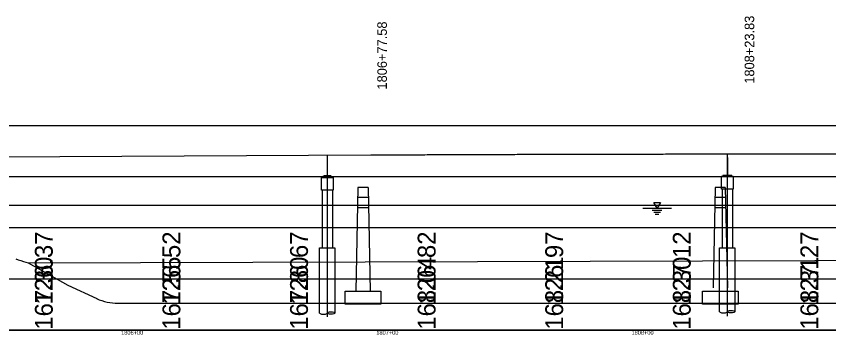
# Model space of a CAD drawing. Extents: x 2126510 to 2136144, y 865066 to 868066.
# Drawn here: x 2129003.4 to 2129321.8, y 866612.1 to 866736.8 of the extents above; entities that cross this region are included whole.
import ezdxf

# ---------------------------------------------------------------- set-up
doc = ezdxf.new("R2010")
doc.units = 0
for name, color, linetype in [('RD_DTM_BkLn1', 7, 'Continuous'), ('RD_EX_BldgApp', 7, 'Continuous'), ('RD_EX_Bridge', 7, 'Continuous'), ('RD_EX_GuardRail', 7, 'Continuous'), ('RD_EX_H2O', 7, 'Continuous'), ('RD_EX_Misc', 7, 'Continuous'), ('RD_EX_Misc_Golf_Fairway', 7, 'Continuous'), ('RD_HC_Data', 7, 'Continuous'), ('RD_HC_txCode', 7, 'Continuous')]:
    doc.layers.add(name, color=color, linetype=linetype)

msp = doc.modelspace()

# ---------------------------------------------------------------- linework, layer by layer
at = {"layer": 'RD_DTM_BkLn1'}
for p, q in [((2129127.05, 866674.01), (2129123.55, 866674.01)), ((2129123.55, 866674.01), (2129123.55, 866673.68)), ((2129126.63, 866674.3), (2129123.96, 866674.3)), ((2129123.96, 866674.01), (2129126.63, 866674.01)), ((2129127.05, 866673.68), (2129127.05, 866674.01)), ((2129280.3, 866674.48), (2129280.3, 866674.15)), ((2129281.71, 866674.48), (2129280.3, 866674.48)), ((2129280.71, 866674.48), (2129283.38, 866674.48)), ((2129283.8, 866674.48), (2129282.05, 866674.48)), ((2129283.8, 866674.15), (2129283.8, 866674.48)), ((2129123.3, 866668.68), (2129123.3, 866646.1)), ((2129127.3, 866668.68), (2129127.3, 866646.1)), ((2129280.05, 866669.15), (2129280.05, 866646.1)), ((2129284.05, 866669.15), (2129284.05, 866646.1))]:
    msp.add_line(p, q, dxfattribs=at)
for points in [[(2129123.05, 866673.68), (2129127.55, 866673.68), (2129127.55, 866668.68), (2129123.05, 866668.68)], [(2129279.8, 866674.15), (2129284.3, 866674.15), (2129284.3, 866669.15), (2129279.8, 866669.15)]]:
    msp.add_lwpolyline(points, close=True, dxfattribs=at)
for points in [[(2129122.3, 866620.57), (2129122.3, 866646.1), (2129128.3, 866646.1), (2129128.3, 866620.57)], [(2129279.05, 866621.11), (2129279.05, 866646.1), (2129285.05, 866646.1), (2129285.05, 866621.11)]]:
    msp.add_lwpolyline(points, dxfattribs=at)
for centre in [(2129123.8, 866620.57), (2129280.55, 866621.11)]:
    msp.add_ellipse(centre, major_axis=(-1.5, 0), ratio=0.310397, start_param=0, end_param=3.141593, dxfattribs=at)
for centre in [(2129126.8, 866620.57), (2129283.55, 866621.11)]:
    msp.add_ellipse(centre, major_axis=(-1.5, 0), ratio=0.310397, dxfattribs=at)
at = {"layer": 'RD_EX_BldgApp'}
for p, q in [((2129253.23, 866663.87), (2129255.85, 866663.87)), ((2129254.54, 866661.6), (2129253.23, 866663.87)), ((2129255.85, 866663.87), (2129254.54, 866661.6)), ((2129248.92, 866661.6), (2129260.17, 866661.6)), ((2129252.67, 866660.85), (2129256.42, 866660.85)), ((2129253.23, 866660.1), (2129255.85, 866660.1)), ((2129253.79, 866659.35), (2129255.29, 866659.35))]:
    msp.add_line(p, q, dxfattribs=at)
at = {"layer": 'RD_EX_Bridge'}
for p, q in [((2129123.96, 866674.3), (2129123.96, 866674.01)), ((2129126.63, 866674.01), (2129126.63, 866674.3)), ((2129280.71, 866674.78), (2129280.71, 866674.48)), ((2129281.71, 866674.78), (2129281.71, 866674.48)), ((2129282.38, 866674.48), (2129282.38, 866674.78)), ((2129283.38, 866674.48), (2129283.38, 866674.78))]:
    msp.add_line(p, q, dxfattribs=at)
at = {"layer": 'RD_EX_GuardRail'}
for p, q in [((2131097.7, 866693.9), (2126517.45, 866693.9)), ((2131097.7, 866673.9), (2129000.13, 866673.9)), ((2131097.7, 866653.9), (2126517.45, 866653.9)), ((2131097.7, 866633.9), (2126517.45, 866633.9)), ((2131097.7, 866613.9), (2126517.45, 866613.9))]:
    msp.add_line(p, q, dxfattribs=at)
at = {"layer": 'RD_EX_H2O'}
msp.add_line((2129043.31, 866624.4), (2129361.63, 866624.4), dxfattribs=at)
for points in [[(2129003.19, 866641.8), (2129004.19, 866641.48), (2129005.19, 866641.15), (2129006.19, 866640.83), (2129007.19, 866640.51), (2129008.03, 866640.24)], [(2129008.03, 866640.24), (2129023.67, 866631.45), (2129034.93, 866626.25)]]:
    msp.add_lwpolyline(points, dxfattribs=at)
msp.add_arc((2129043.31, 866644.4), 20, 245.2113, 270, dxfattribs=at)
at = {"layer": 'RD_EX_Misc'}
for p, q in [((2127961.73, 866676.62), (2129142.37, 866682.52)), ((2127368.72, 866613.9), (2131522.97, 866613.9))]:
    msp.add_line(p, q, dxfattribs=at)
for points in [[(2127275.85, 866613.9), (2127275.85, 866662.9), (2131989.68, 866662.9)], [(2129008.05, 866640.24), (2129404.47, 866641.43)]]:
    msp.add_lwpolyline(points, dxfattribs=at)
msp.add_spline([(2129142.37, 866682.52), (2129149.42, 866682.56), (2129156.47, 866682.59), (2129163.52, 866682.62), (2129170.57, 866682.65), (2129177.62, 866682.68), (2129184.67, 866682.7), (2129191.72, 866682.73), (2129198.77, 866682.75), (2129205.82, 866682.77), (2129212.87, 866682.79), (2129219.92, 866682.81), (2129226.97, 866682.83), (2129234.02, 866682.85), (2129241.07, 866682.86), (2129248.12, 866682.87), (2129255.17, 866682.88), (2129262.23, 866682.89), (2129269.28, 866682.9), (2129276.33, 866682.9), (2129283.38, 866682.91), (2129290.43, 866682.91), (2129297.48, 866682.91), (2129304.53, 866682.91), (2129311.58, 866682.91), (2129318.63, 866682.9), (2129325.68, 866682.9), (2129332.73, 866682.89), (2129339.78, 866682.88), (2129346.83, 866682.87), (2129353.88, 866682.86), (2129360.93, 866682.85), (2129367.98, 866682.83), (2129375.03, 866682.82), (2129382.08, 866682.8), (2129389.13, 866682.78), (2129396.18, 866682.76), (2129403.23, 866682.74), (2129410.28, 866682.71), (2129417.33, 866682.68), (2129424.38, 866682.66), (2129431.43, 866682.63), (2129438.48, 866682.6), (2129445.53, 866682.56), (2129452.58, 866682.53), (2129459.63, 866682.49), (2129466.68, 866682.46), (2129473.73, 866682.42), (2129480.78, 866682.38), (2129487.83, 866682.34), (2129494.88, 866682.29)], degree=3, dxfattribs=at)
at = {"layer": 'RD_EX_Misc_Golf_Fairway'}
for p, q in [((2129137.28, 866669.78), (2129136.44, 866629.1)), ((2129141.28, 866669.78), (2129137.28, 866669.78)), ((2129141.28, 866669.78), (2129142.13, 866629.1)), ((2129277.28, 866669.78), (2129276.46, 866630.4)), ((2129281.28, 866669.78), (2129277.28, 866669.78)), ((2129281.28, 866669.78), (2129282.1, 866630.4)), ((2129141.37, 866665.78), (2129137.21, 866665.78)), ((2129281.37, 866665.78), (2129277.21, 866665.78)), ((2129141.45, 866661.78), (2129137.12, 866661.78)), ((2129281.45, 866661.78), (2129277.12, 866661.78))]:
    msp.add_line(p, q, dxfattribs=at)
for points in [[(2129132.28, 866629.1), (2129146.28, 866629.1), (2129146.28, 866624.1), (2129132.28, 866624.1)], [(2129272.28, 866629.1), (2129286.28, 866629.1), (2129286.28, 866624.1), (2129272.28, 866624.1)]]:
    msp.add_lwpolyline(points, close=True, dxfattribs=at)
at = {"layer": 'RD_HC_Data'}
for p, q in [((2129282.05, 866682.91), (2129282.05, 866619.34)), ((2129125.3, 866682.44), (2129125.3, 866619.14))]:
    msp.add_line(p, q, dxfattribs=at)
at = {"layer": 'RD_HC_txCode'}
for p, q in [((2129281.96, 866681.48), (2129281.96, 866674.78)), ((2129282.13, 866681.48), (2129282.13, 866674.78))]:
    msp.add_line(p, q, dxfattribs=at)

# ---------------------------------------------------------------- texts
at = {"layer": 'RD_EX_Misc'}
for s, height, p in [('1808+23.83', 3.75, (2129292.61, 866710.43)), ('1806+77.58', 3.75, (2129148.65, 866708.14)), ('126.37', 7, (2129017.72, 866623.9)), ('126.52', 7, (2129067.72, 866623.9)), ('126.67', 7, (2129117.72, 866623.9)), ('126.82', 7, (2129167.72, 866623.9)), ('126.97', 7, (2129217.72, 866623.9)), ('127.12', 7, (2129267.72, 866623.9)), ('127.27', 7, (2129317.72, 866623.9)), ('167.30', 7, (2129017.72, 866614.05)), ('167.55', 7, (2129067.72, 866614.05)), ('167.80', 7, (2129117.72, 866614.05)), ('168.04', 7, (2129167.72, 866614.05)), ('168.21', 7, (2129217.72, 866614.05)), ('168.30', 7, (2129267.72, 866614.05)), ('168.31', 7, (2129317.72, 866614.05))]:
    msp.add_text(s, height=height, rotation=90, dxfattribs=at).set_placement(p)
for s, p in [('1806+00', (2129044.51, 866612.1)), ('1807+00', (2129144.51, 866612.1)), ('1808+00', (2129244.51, 866612.1))]:
    msp.add_text(s, height=1.6, dxfattribs=at).set_placement(p)

doc.saveas('drawing.dxf')
